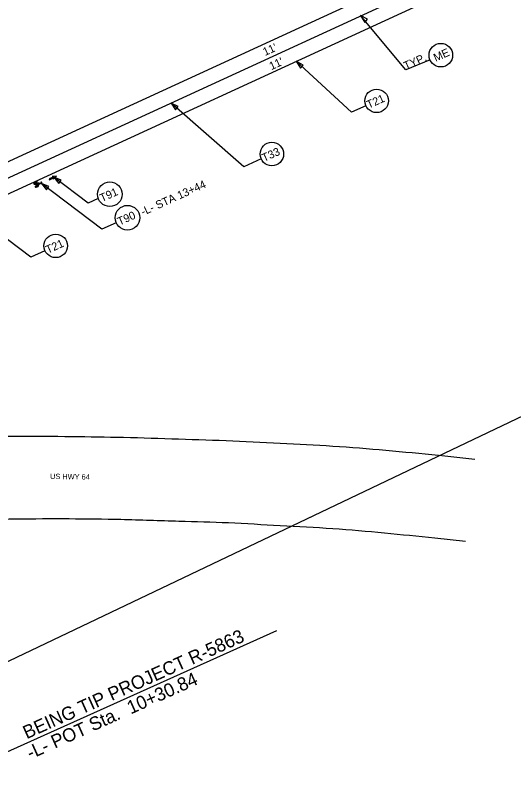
# Model space of a CAD drawing. Extents: x 553958 to 562499, y 493978 to 516388.
# Drawn here: x 554688 to 555061, y 502854 to 503433 of the extents above; entities that cross this region are included whole.
import ezdxf

# ---------------------------------------------------------------- set-up
doc = ezdxf.new("R2010")
doc.units = 0
for name, color, linetype in [('Default', 7, 'Continuous'), ('Prop Approach Slab', 7, 'Continuous'), ('Prop EOT', 7, 'Continuous'), ('Prop Erosion Rip Rap Class II Label', 7, 'Continuous'), ('Prop Horizontal Alignment Tick Small', 7, 'Continuous'), ('Prop Roadway Bridge', 7, 'Continuous'), ('Raster_Level_0', 7, 'Continuous'), ('Sheet Plan CELL', 7, 'Continuous'), ('Sheet Plot Border Inside CELL', 7, 'Continuous')]:
    doc.layers.add(name, color=color, linetype=linetype)

msp = doc.modelspace()

# ---------------------------------------------------------------- linework, layer by layer
at = {"layer": 'Prop Approach Slab'}
msp.add_line((554671.05, 502877.26), (554883.52, 502972.67), dxfattribs=at)
at = {"layer": 'Prop Erosion Rip Rap Class II Label'}
msp.add_lwpolyline([(555793.48, 503466.69), (555600.74, 503885.63), (555438.59, 504238.1), (554125.45, 503648.45), (554482.04, 502854.33), (555335.17, 503260.89)], close=True, dxfattribs=at)
at = {"layer": 'Prop Horizontal Alignment Tick Small'}
for p, q in [((554702.62, 503308.21), (554702.52, 503308.44)), ((554702.62, 503308.21), (554702.52, 503308.44)), ((554703.05, 503307.25), (554702.96, 503307.47)), ((554703.05, 503307.25), (554702.96, 503307.47)), ((554703.09, 503306.56), (554703.04, 503306.8)), ((554703.07, 503306.8), (554705.05, 503306.97)), ((554705.2, 503306.74), (554703.09, 503306.56)), ((554703.62, 503305.98), (554703.52, 503306.21)), ((554703.62, 503305.98), (554703.52, 503306.21)), ((554703.82, 503307.31), (554704.5, 503307.8)), ((554703.96, 503307.11), (554703.82, 503307.31)), ((554704.48, 503307.5), (554703.96, 503307.11)), ((554704.06, 503305.02), (554703.96, 503305.24)), ((554704.06, 503305.02), (554703.96, 503305.24)), ((554705.05, 503306.97), (554704.48, 503307.5)), ((554704.5, 503307.8), (554705.24, 503307.11)), ((554704.9, 503308.04), (554705.18, 503308.16)), ((554706.21, 503307.62), (554704.9, 503308.04)), ((554705.18, 503308.16), (554706.46, 503307.76)), ((554706.68, 503307.51), (554705.2, 503306.74)), ((554705.24, 503307.11), (554706.21, 503307.62)), ((554706.46, 503307.76), (554706.68, 503307.51)), ((554706.82, 503308.5), (554706.88, 503308.36)), ((554706.82, 503308.5), (554706.88, 503308.36)), ((554707.21, 503307.61), (554707.28, 503307.47)), ((554707.21, 503307.61), (554707.28, 503307.47))]:
    msp.add_line(p, q, dxfattribs=at)
msp.add_lwpolyline([(554715.14, 503312.72), (554716, 503312.35), (554712.9, 503310.96), (554713.16, 503310.38), (554716.26, 503311.77), (554715.97, 503310.88), (554718.51, 503313.13)], close=True, dxfattribs=at)
msp.add_lwpolyline([(554715.14, 503312.72), (554716, 503312.35), (554712.9, 503310.96), (554713.16, 503310.38), (554716.26, 503311.77), (554715.97, 503310.88), (554718.51, 503313.13)], close=True, dxfattribs=at)
for radius, start, end in [(0.41, 114.18158, 294.18158), (0.563, 294.18158, 114.18158), (0.563, 294.18158, 114.18158)]:
    msp.add_arc((554707.05, 503307.98), radius, start, end, dxfattribs=at)
for centre, major_axis, ratio, start_param, end_param in [((554702.79, 503307.84), (-1.36, -0.61), 0.435841, 4.712389, 7.853982), ((554702.79, 503307.84), (-1.14, -0.51), 0.325967, 4.712389, 7.853982), ((554703.79, 503305.61), (-1.36, -0.61), 0.435841, 4.712389, 7.853982), ((554702.79, 503307.84), (-1.36, -0.61), 0.435841, 1.570796, 4.712389), ((554703.79, 503305.61), (-1.14, -0.51), 0.325967, 4.712389, 7.853982), ((554702.79, 503307.84), (-1.14, -0.51), 0.325967, 1.570796, 4.712389), ((554703.79, 503305.61), (-1.36, -0.61), 0.435841, 1.570796, 4.712389), ((554703.79, 503305.61), (-1.14, -0.51), 0.325967, 1.570796, 4.712389)]:
    msp.add_ellipse(centre, major_axis=major_axis, ratio=ratio, start_param=start_param, end_param=end_param, dxfattribs=at)
at = {"layer": 'Prop Roadway Bridge'}
for p, q in [((555032.11, 503100.73), (555009.62, 503103.27)), ((555024.9, 503039.39), (555002.05, 503041.83))]:
    msp.add_line(p, q, dxfattribs=at)
for points in [[(555009.62, 503103.27), (554970.38, 503107.1), (554930.52, 503110.3), (554891.2, 503112.58), (554850.59, 503114.56), (554809.97, 503115.97), (554768.8, 503117.22), (554729.86, 503117.84), (554688.09, 503118.07), (554646.73, 503117.18), (554606.63, 503115.85)], [(555002.05, 503041.83), (554964.24, 503045.65), (554925.55, 503048.89), (554886.08, 503051.15), (554847.29, 503053.26), (554810.28, 503054.49), (554766.79, 503055.75), (554727.94, 503056.26), (554687.99, 503056.08), (554647.36, 503055.32), (554609.74, 503053.99), (554570.3, 503052.17), (554530.42, 503050.16), (554489.62, 503048), (554449.13, 503045.57), (554408.82, 503042.34), (554368.28, 503038.73), (554338.38, 503036.05)]]:
    msp.add_spline(points, degree=3, dxfattribs=at)
at = {"layer": 'Raster_Level_0'}
msp.add_line((554619.25, 503282.9), (555064.66, 503487.54), dxfattribs=at)
at = {"layer": 'Sheet Plan CELL'}
for points in [[(554998.47, 503400.11), (554980.27, 503392.63), (554946.3, 503433.36)], [(554950.32, 503365.84), (554939.49, 503360.98), (554898.14, 503399.1)], [(554871.84, 503326.01), (554858.85, 503320.18), (554804.36, 503367.79)], [(554749.77, 503296.39), (554742.09, 503292.94), (554716.52, 503312.24)], [(554763.25, 503278.18), (554752.56, 503273.37), (554707.21, 503307.61)], [(554709.8, 503257.22), (554699.11, 503252.42), (554653.77, 503286.66)]]:
    msp.add_lwpolyline(points, dxfattribs=at)
for points in [[(554951.61, 503430.57), (554946.3, 503433.36), (554949.51, 503428.29)], [(554903.45, 503396.31), (554898.14, 503399.1), (554901.35, 503394.03)], [(554809.75, 503365.14), (554804.36, 503367.79), (554807.7, 503362.81)], [(554722.08, 503309.99), (554716.52, 503312.24), (554720.21, 503307.51)], [(554712.78, 503305.36), (554707.21, 503307.61), (554710.9, 503302.88)]]:
    msp.add_lwpolyline(points, close=True, dxfattribs=at)
for centre, radius in [((555006.53, 503403.72), 8.82), ((554958.37, 503369.46), 8.82), ((554879.89, 503329.63), 8.82), ((554758.44, 503299.52), 9.22), ((554771.66, 503281.95), 9.22), ((554717.86, 503260.84), 8.82)]:
    msp.add_circle(centre, radius, dxfattribs=at)
at = {"layer": 'Sheet Plot Border Inside CELL'}
for p, q in [((554614.65, 503292.9), (555559.74, 503727.68)), ((554623.85, 503272.91), (555048.71, 503468.37))]:
    msp.add_line(p, q, dxfattribs=at)

# ---------------------------------------------------------------- texts
at = {"layer": 'Default'}
msp.add_text('US HWY 64', height=4, rotation=359.0144, dxfattribs=at).set_placement((554713.62, 503086.25))
at = {"layer": 'Prop Approach Slab'}
for s, p in [(' BEING TIP PROJECT R-5863', (554692.71, 502889.67)), ('-L- POT Sta.  10+30.84', (554698.86, 502875.98))]:
    msp.add_text(s, height=10, rotation=24.18158, dxfattribs=at).set_placement(p)
at = {"layer": 'Prop EOT'}
for p in [(554874.75, 503403.06), (554879.52, 503392.44)]:
    msp.add_text("11'", height=6, rotation=24.18158, dxfattribs=at).set_placement(p)
at = {"layer": 'Sheet Plan CELL'}
for s, p in [('ME', (555002.67, 503398.7)), ('TYP.', (554980.27, 503392.63)), ('T21', (554952.48, 503363.53)), ('T33', (554874.01, 503323.7)), ('-L- STA 13+44', (554783.35, 503283.35)), ('T91', (554752.52, 503293.58)), ('T90', (554765.75, 503276.01)), ('T21', (554711.97, 503254.91))]:
    msp.add_text(s, height=6, rotation=24.18158, dxfattribs=at).set_placement(p)

doc.saveas('drawing.dxf')
